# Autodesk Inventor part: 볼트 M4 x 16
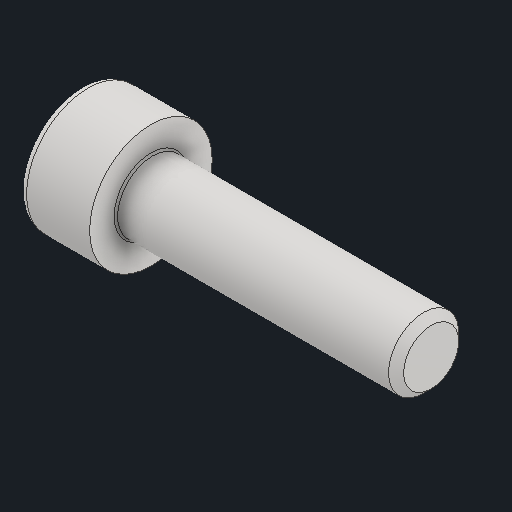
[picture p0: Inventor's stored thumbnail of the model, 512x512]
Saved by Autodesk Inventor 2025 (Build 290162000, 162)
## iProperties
Created: 2025-08
Part Number: 볼트 M4 x 16
Material: 스테인리스강
Description: 6각 소켓 머리 캡 나사
Document SubType Name: Modeling
Designer: infra027
Density: 8.08 g/cm^3
Appearance: 기본값
Author: jhkim
Sending System: Autodesk Inventor 2026
Preprocessor: ST-DEVELOPER v20.1
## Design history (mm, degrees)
feature "Solid1"
node "솔리드1"
